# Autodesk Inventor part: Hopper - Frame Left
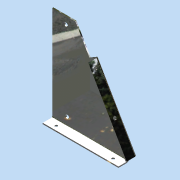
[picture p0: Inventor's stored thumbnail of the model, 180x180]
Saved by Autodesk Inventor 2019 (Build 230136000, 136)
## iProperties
Created: 2005-11
Part Number: Hopper - Frame Left
Document SubType Name: Sheet Metal
Designer: floress
Material: Aluminum 6061
Density: 2.7 g/cm^3
Sheet Metal Rule: Default
Appearance: Aluminum - Flat
Flat Pattern Width: 12.2582 cm
Flat Pattern Length: 14.0116 cm
Flat Pattern Area: 171.757 cm^2
Sheet Metal Width: 4.826 in
Sheet Metal Length: 5.516 in
Sheet Metal Area: 26.622 in^2
Author: floress
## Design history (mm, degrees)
node "Face1"
  sketch "Sketch1"
    geometry: L1 (-67.125, 63.5)-(-36.06, 63.5); L2 (34.475, -63.5)-(-67.125, -63.5); L3 (-67.125, -63.5)-(-67.125, 63.5); L4 (-36.06, 63.5)-(-17.01, 30.504); L5 (-17.01, 30.504)-(-6.012, 36.854); L6 (-6.012, 36.854)-(45.473, -52.321); L7 (34.475, -63.5)-(34.475, -58.671); L8 (34.475, -58.671)-(45.473, -52.321); 3 further points
    constraints: 16 end point, 4 parallel, 3 perpendicular, 1 horizontal, 1 horizontal alignment, 1 midpoint, 1 vertical alignment
    dimensions: "d1" = 127 distance of L2.end L1.start; "d2" = 12.7 distance of L4.end L5.end; "d3" = 38.1 distance of L1.end L4.end; "d4" = 60 deg angle of L2 L6; "d20" = 101.6 distance of L2.start L2.end; "d32" = 4.82949 distance of L2.start L7.end; "d33" = 12.7 distance of L7.end L6.end (derived)
node "Flange1"
node "Flange2"
sketch "Sketch4"
  geometry: C1 r 2.5 at (18.641, -9.97) reference; C2 r 2.5 at (20.152, -116.253) reference
cut "Cut1" sketch "Sketch4" dims "d21" = 1.5875 (= Thickness), "d22" = 0
sketch "Sketch5"
  geometry: L1 (101.6, 0)-(101.6, -11.112) reference; L2 (0, -11.113)-(0, 0) reference; C1 r 1.778 at (12.7, -5.556); C2 r 1.778 at (88.9, -5.556); 1 further point
  constraints: 2 centre point, 2 horizontal alignment, 1 equal radius, 1 midpoint
  dimensions: "d23" = 3.556 diameter of C1; "d24" = 12.7 distance from line of L2 C1.centre; "d25" = 12.7 distance from line of C2.centre L1
cut "Cut2" sketch "Sketch5" dims "d26" = 1.5875 (= Thickness), "d27" = 0
sketch "Sketch6"
  geometry: L1 (0, 102.97)-(11.112, 102.97) reference; C1 r 2.159 at (5.556, 94.365); C2 r 2.159 at (5.556, 42.871); 1 further point
  constraints: 2 centre point, 2 vertical alignment, 1 equal radius, 1 midpoint
  dimensions: "d28" = 4.318 diameter of C1; "d31" = 8.60515 distance from line of L1 C1.centre
cut "Cut3" sketch "Sketch6" dims "d29" = 1.5875 (= Thickness), "d30" = 0
body "Solid1"
face "Plate1" dims "d34" = 1.5875 (= Thickness)
sketch "Sketch2"
  geometry: L1 through (50.8, 0) direction (1, 0); L2 (101.6, 0)-(101.6, 12.7); L3 (101.6, 12.7)-(0, 12.7); L4 through (0, 6.35) direction (0, -1)
  constraints: 6 end point, 1 horizontal, 1 perpendicular, 1 vertical
face "Plate2" dims "d6" = 1.5875 (= BendReliefWidth), "d8" = 3.175 (= MinimumRemnant), "d10" = 12.7, "d11" = 90 deg, "d12" = 1.5875 (= BendRadius), "d34" = 1.5875 (= Thickness)
bend "Bend1" dims "d6" = 1.5875 (= BendReliefWidth), "d7" = 0.79375 (= BendReliefDepth), "d8" = 3.175 (= MinimumRemnant), "d9" = 1.5875 (= BendRadius), "d10" = 12.7, "d11" = 90 deg, "d12" = 1.5875 (= BendRadius), "d34" = 1.5875 (= Thickness), "SeamGap" = 0.00508
sketch "Sketch3"
  geometry: L1 through (51.485, 0) direction (1, 0); L2 (102.97, 0)-(102.97, 12.7); L3 (102.97, 12.7)-(0, 12.7); L4 through (0, 6.35) direction (-3.47e-16, -1)
  constraints: 6 end point, 1 horizontal, 1 perpendicular, 1 vertical
face "Plate3" dims "d13" = 1.5875 (= BendReliefWidth), "d15" = 3.175 (= MinimumRemnant), "d17" = 12.7, "d18" = 90 deg, "d19" = 1.5875 (= BendRadius), "d34" = 1.5875 (= Thickness)
bend "Bend2" dims "d13" = 1.5875 (= BendReliefWidth), "d14" = 0.79375 (= BendReliefDepth), "d15" = 3.175 (= MinimumRemnant), "d16" = 1.5875 (= BendRadius), "d17" = 12.7, "d18" = 90 deg, "d19" = 1.5875 (= BendRadius), "d34" = 1.5875 (= Thickness), "SeamGap" = 0.00508
node "Reference1"
node "Reference2"
feature "Definition1"
other parameters: "Thickness" = 1.5875, "BendRadius" = 1.5875 (= Thickness), "BendReliefWidth" = 1.5875 (= Thickness), "BendReliefDepth" = 0.79375 (= 0.5 x Thickness), "CornerReliefSize" = 6.35 (= 4 x Thickness), "MinimumRemnant" = 3.175 (= 2 x Thickness), "TransitionRadius" = 1.5875 (= BendRadius), "d5" = 1.5875 (= BendRadius), "JacobiRadiusSize" = 1.5875 (= Thickness), "GapSize" = 1.5875 (= Thickness), "BendRadius" = 1.5875, "BendReliefDepth" = 0.79375, "BendReliefWidth" = 1.5875, "CornerReliefSize" = 6.35, "GapSize" = 1.5875, "JacobiRadiusSize" = 1.5875, "MinimumRemnant" = 3.175, "Thickness" = 1.5875, "TransitionRadius" = 1.5875
